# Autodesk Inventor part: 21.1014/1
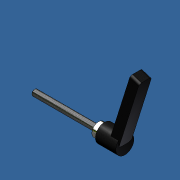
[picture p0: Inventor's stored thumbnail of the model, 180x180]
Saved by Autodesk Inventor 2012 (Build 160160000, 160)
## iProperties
Created: 2007-06
Part Number: 21.1014/1
Document SubType Name: Modeling
Designer: Andy Moles
Material: Steel
Mass: 124.358 g
Surface Area: 60.2141 cm^2
Volume: 15.8418 cm^3
Density: 7.85 g/cm^3
Description: SLIDE LOCK WITH M6X65 STUD
Vendor: S
Author: Andy Moles
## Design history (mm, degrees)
feature "Base1"
sketch "Sketch1"
  geometry: C1 r 6.731 at (0, 0) reference; C2 r 3 at (0, 0)
  constraints: 1 centre point, 1 coincident
  dimensions: "d0" = 6 diameter of C2
extrude "Extrusion1" join sketch "Sketch1" distance "d1" = 65; taper "d2" = 0 deg
thread "Thread1" dims "d3" = 10, "d4" = 0
chamfer "Chamfer1" distance "d5" = 0.5; stored, may be unused: second distance "d6" = 2, angle "d7" = 45 deg
body "Solid1"
other parameters: "STUD_LENGTH" = 65 [user parameter]
